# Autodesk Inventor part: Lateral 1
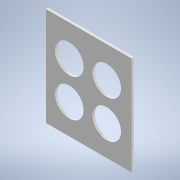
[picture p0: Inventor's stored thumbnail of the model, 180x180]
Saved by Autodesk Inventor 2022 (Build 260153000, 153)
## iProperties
Created: 2022-02
Part Number: Lateral 1
Material: Genérico
Document SubType Name: Modeling
Designer: pined
Density: 1 g/cm^3
Appearance: Valor por defecto
Author: pined
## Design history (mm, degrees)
sketch "Boceto1"
  geometry: L1 (-30, 2.5)-(57, 2.5); L2 (57, 2.5)-(57, 89.5); L3 (57, 89.5)-(-30, 89.5); L4 (-30, 89.5)-(-30, 2.5); L5 (-30, 89.5)-(57, 2.5); L6 (-36.5, -4)-(63.5, -4); L7 (63.5, -4)-(63.5, 96); L8 (63.5, 96)-(-36.5, 96); L9 (-36.5, 96)-(-36.5, -4); L10 (-36.5, -4)-(63.5, 96); L11 (63.5, -4)-(-36.5, 96); L12 (-20, 0)-(0, 0) reference; L13 (0, 0)-(0, 2.5) reference; L14 (-20, 2.5)-(0, 2.5) reference; L15 (-20, 0)-(-20, 2.5) reference; L16 (30, 0)-(50, 0) reference; L17 (50, 0)-(50, 2.5) reference; L18 (30, 2.5)-(50, 2.5) reference; L19 (30, 0)-(30, 2.5) reference; L20 (30, 2.5)-(50, 2.5); L21 (-20, 0)-(0, 0); L22 (0, 0)-(0, 2.5); L23 (0, 2.5)-(-20, 2.5); L24 (-20, 2.5)-(-20, 0); L25 (30, 0)-(50, 0); L26 (50, 0)-(50, 2.5); L27 (50, 2.5)-(30, 2.5); L28 (30, 2.5)-(30, 0); L29 (59.5, 12.5)-(59.5, 32.5); L30 (57, 12.5)-(59.5, 12.5); L31 (57, 32.5)-(57, 12.5); L32 (59.5, 32.5)-(57, 32.5); L33 (57, 82.5)-(57, 62.5); L34 (57, 62.5)-(59.5, 62.5); L35 (59.5, 62.5)-(59.5, 82.5); L36 (59.5, 82.5)-(57, 82.5); L37 (47, 92)-(27, 92); L38 (47, 89.5)-(47, 92); L39 (27, 89.5)-(47, 89.5); L40 (27, 92)-(27, 89.5); L41 (-23, 89.5)-(-3, 89.5); L42 (-3, 89.5)-(-3, 92); L43 (-3, 92)-(-23, 92); L44 (-23, 92)-(-23, 89.5); L45 (-32.5, 79.5)-(-32.5, 59.5); L46 (-30, 79.5)-(-32.5, 79.5); L47 (-30, 59.5)-(-30, 79.5); L48 (-32.5, 59.5)-(-30, 59.5); L49 (-30, 9.5)-(-30, 29.5); L50 (-30, 29.5)-(-32.5, 29.5); L51 (-32.5, 29.5)-(-32.5, 9.5); L52 (-32.5, 9.5)-(-30, 9.5); 1 further point
  constraints: 88 end point, 8 parallel, 4 horizontal, 4 perpendicular, 3 midpoint, 1 collinear, 66 other
  dimensions: "d0" = 87 distance of L3.end L2.end; "d1" = 87 distance of L2.end L1.end; "d2" = 100 distance of L8.end L7.end; "d3" = 100 distance of L7.end L6.end; "d6" = 360 deg dimension on point (13.5, 46) L12.start (derived)
extrude "Extrusión1" new body sketch "Boceto1" distance "d8" = 2.5; taper "d9" = 0 deg
sketch "Sketch4"
  geometry: L1 (63.5, 96)-(-36.5, 96) reference; L2 (-36.5, -4)-(63.5, -4) reference; L3 (-36.5, 96)-(-31.5, 96); L4 (-31.5, 96)-(-31.5, -4); L5 (-31.5, -4)-(-36.5, -4); L6 (-36.5, -4)-(-36.5, 96); L7 (63.5, -4)-(63.5, 96) reference; L8 (63.5, 96)-(58.5, 96); L9 (58.5, 96)-(58.5, -4); L10 (58.5, -4)-(63.5, -4); L11 (63.5, -4)-(63.5, 96); 5 further points
  constraints: 16 end point, 4 parallel, 2 horizontal, 2 perpendicular, 2 point on line
  dimensions: "d17" = 5 distance of L4.end L5.end; "d18" = 5 distance of L10.end L9.end
extrude "Extrusion4" cut sketch "Sketch4" distance "d19" = 2.5; taper "d20" = 0 deg
sketch "Sketch5"
  geometry: L1 (-30, 79.5)-(-30, 59.5) reference; L2 (-31.5, 9.5)-(-31.5, -4) reference; L3 (-30, 79.5)-(-31.5, 79.5); L4 (-31.5, 79.5)-(-31.5, 9.5); L5 (-31.5, 9.5)-(-30, 9.5); L6 (-30, 9.5)-(-30, 79.5); L7 (57, 62.5)-(57, 82.5) reference; L8 (58.5, -4)-(58.5, 12.5) reference; L9 (57, 82.5)-(58.5, 82.5); L10 (58.5, 82.5)-(58.5, 12.5); L11 (58.5, 12.5)-(57, 12.5); L12 (57, 12.5)-(57, 82.5); 3 further points
  constraints: 16 end point, 4 parallel, 2 horizontal, 2 perpendicular
extrude "Extrusion5" join sketch "Sketch5" distance "d21" = 2.5; taper "d22" = 0 deg
sketch "Sketch7"
  geometry: L1 (58.5, 96)-(-31.5, 96) reference; L2 (-31.5, -4)-(58.5, -4) reference; L3 (47, 92)-(47, 89.5) reference; L4 (47, 89.5)-(27, 89.5) reference; L5 (27, 89.5)-(27, 92) reference; L6 (27, 92)-(47, 92) reference; L7 (-23, 89.5)-(-23, 92) reference; L8 (-23, 92)-(-3, 92) reference; L9 (-3, 92)-(-3, 89.5) reference; L10 (-3, 89.5)-(-23, 89.5) reference; L11 (30, 2.5)-(50, 2.5) reference; L12 (50, 2.5)-(50, 0) reference; L13 (50, 0)-(30, 0) reference; L14 (30, 0)-(30, 2.5) reference; L15 (-20, 0)-(-20, 2.5) reference; L16 (-20, 2.5)-(0, 2.5) reference; L17 (0, 2.5)-(0, 0) reference; L18 (0, 0)-(-20, 0) reference; L19 (58.5, -4)-(58.5, 96) reference; L20 (-31.5, 96)-(-31.5, -4) reference; 1 further point
extrude "Extrusion7" join sketch "Sketch7" distance "d33" = 2.5; taper "d34" = 0 deg
sketch "Sketch8"
  geometry: L1 (0, 0)-(20, 0) reference; L2 (20, 2.5)-(0, 2.5) reference; L3 (20, 0)-(20, 2.5) reference; L4 (0, 2.5)-(0, 0) reference; L5 (-27, 2.5)-(-47, 2.5) reference; L6 (-27, 0)-(-27, 2.5) reference; L7 (-47, 0)-(-27, 0) reference; L8 (-47, 2.5)-(-47, 0) reference; L9 (20, 92)-(0, 92) reference; L10 (20, 89.5)-(20, 92) reference; L11 (0, 89.5)-(20, 89.5) reference; L12 (0, 92)-(0, 89.5) reference; L13 (-47, 89.5)-(-27, 89.5) reference; L14 (-27, 89.5)-(-27, 92) reference; L15 (-27, 92)-(-47, 92) reference; L16 (-47, 92)-(-47, 89.5) reference
  constraints: 32 end point, 8 horizontal, 8 vertical, 16 other
extrude "Extrusion8" cut sketch "Sketch8" distance "d35" = 2.5; taper "d36" = 0 deg
sketch "Sketch9"
  geometry: L1 (-27, 2.5)-(-47, 2.5) reference; L2 (0, 89.5)-(20, 89.5) reference; L3 (-47, 2.5)-(20, 89.5); L4 (-57, 2.5)-(30, 2.5); L5 (30, 2.5)-(30, 89.5); L6 (30, 89.5)-(-57, 89.5); L7 (-57, 89.5)-(-57, 2.5); L8 (-57, 2.5)-(30, 89.5); L9 (30, 2.5)-(-57, 89.5); L10 (-57, 2.5)-(-13.5, 46); L11 (-13.5, 46)-(-57, 89.5); L12 (-13.5, 46)-(30, 89.5); L13 (-13.5, 46)-(30, 2.5); L14 (-35.25, 24.25)-(-31.714, 27.786); L15 (-35.25, 67.75)-(-31.714, 64.214); L16 (8.25, 67.75)-(4.714, 64.214); L17 (8.25, 24.25)-(4.714, 27.786); L18 (-58.5, 96)-(31.5, 96) reference; L19 (31.5, -4)-(-58.5, -4) reference; L20 (-58.5, 96)-(-57, 96); L21 (-57, 96)-(-57, -4); L22 (-57, -4)-(-58.5, -4); L23 (-58.5, -4)-(-58.5, 96); L24 (31.5, -4)-(31.5, 96) reference; L25 (30, -4)-(31.5, -4); L26 (31.5, -4)-(31.5, 96); L27 (31.5, 96)-(30, 96); L28 (30, 96)-(30, -4); C1 r 14.5 at (-31.714, 64.214); C2 r 14.5 at (4.714, 64.214); C3 r 14.5 at (-31.714, 27.786); C4 r 14.5 at (4.714, 27.786); 5 further points
  constraints: 46 end point, 7 midpoint, 7 point on line, 6 parallel, 4 centre point, 4 coincident, 3 horizontal, 3 perpendicular, 1 collinear
  dimensions: "d37" = 87 distance of L6.end L5.end; "d38" = 5 distance of L14.start L14.end; "d39" = 5 distance of L15.start L15.end; "d40" = 5 distance of L16.start L16.end; "d41" = 5 distance of L17.start L17.end; "d42" = 29 diameter of C1; "d43" = 29 diameter of C2; "d44" = 29 diameter of C3; "d45" = 29 diameter of C4
extrude "Extrusion9" cut sketch "Sketch9" distance "d46" = 5 (= d39); taper "d47" = 0 deg
node "Sólido1"
node "Referencia1"
node "Referencia2"
node "Projected Loop1"
